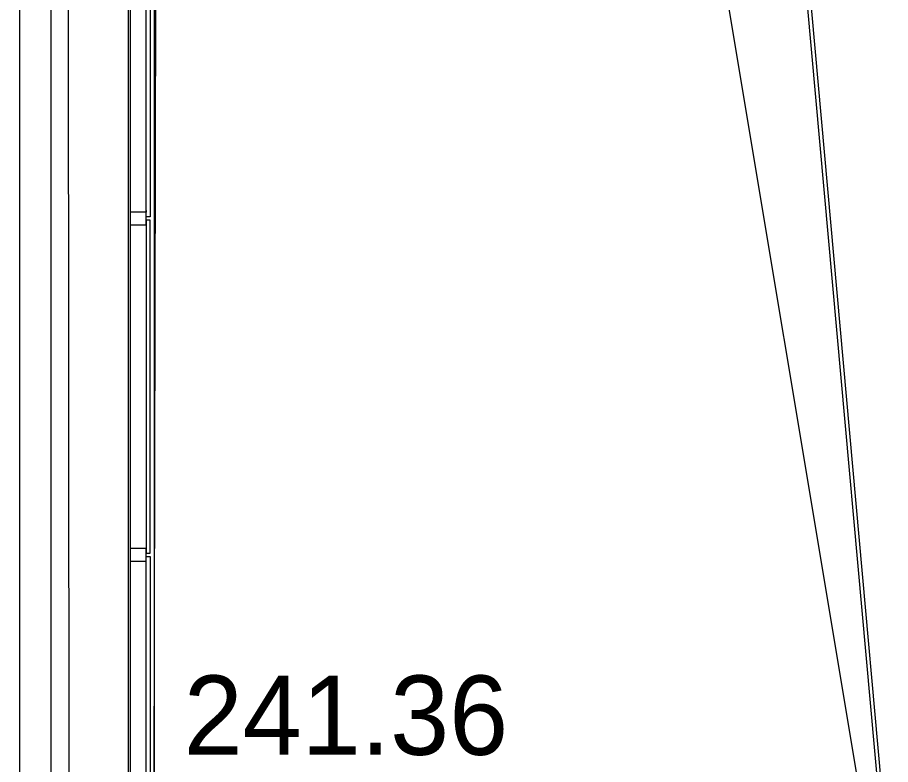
# Model space of a CAD drawing. Extents: x -264205 to -263659, y -1242401 to -1242060.
# Drawn here: x -263795.75 to -263790.25, y -1242194.76 to -1242190.06 of the extents above; entities that cross this region are included whole.
import ezdxf

# ---------------------------------------------------------------- set-up
doc = ezdxf.new("R2010")
doc.units = 0
for name, color, linetype in [('BOD_VYSKA', 7, 'Continuous'), ('KFA_SO_10-1_PLACHTY', 7, 'Continuous'), ('KFA_SO_10-1_STRECHY', 7, 'Continuous'), ('KFA_SO_10-1_TRIBUNA_C_OBVOD', 7, 'Continuous'), ('OBRUBNIKY_KOMUNIKACIE_PROJEKT', 7, 'Continuous'), ('OSI_STAVBY_KFA', 7, 'Continuous'), ('SITUACIA_DSP_2D', 7, 'Continuous')]:
    doc.layers.add(name, color=color, linetype=linetype)

msp = doc.modelspace()

# ---------------------------------------------------------------- linework, layer by layer
at = {"layer": 'KFA_SO_10-1_PLACHTY'}
msp.add_line((-263794.893, -1242195.596), (-263794.843, -1242168.189), dxfattribs=at)
for points in [[(-263795.396, -1242226.823), (-263795.427, -1242195.892), (-263795.456, -1242167.905), (-263795.427, -1242160.909), (-263795.402, -1242132.887), (-263795.428, -1242101.98)], [(-263790.3646, -1242195.4172), (-263794.826, -1242168.6678), (-263794.862, -1242168.412)]]:
    msp.add_lwpolyline(points, dxfattribs=at)
msp.add_lwpolyline([(-263792.74, -1242168.185), (-263792.715, -1242168.173), (-263790.251, -1242195.546), (-263790.271, -1242195.563)], close=True, dxfattribs=at)
at = {"layer": 'KFA_SO_10-1_STRECHY'}
msp.add_line((-263795.734, -1242227.196), (-263795.754, -1242101.588), dxfattribs=at)
at = {"layer": 'KFA_SO_10-1_TRIBUNA_C_OBVOD'}
msp.add_lwpolyline([(-263795.284, -1242101.267), (-263795.051, -1242101.819), (-263795.059, -1242226.991), (-263795.286, -1242227.548)], dxfattribs=at)
at = {"layer": 'OBRUBNIKY_KOMUNIKACIE_PROJEKT'}
msp.add_line((-263794.8928, -1242101.3822), (-263794.8928, -1242227.3822), dxfattribs=at)
at = {"layer": 'OSI_STAVBY_KFA'}
msp.add_line((-263795.5428, -1242083.2372), (-263795.5428, -1242246.7072), dxfattribs=at)
at = {"layer": 'SITUACIA_DSP_2D'}
for p, q in [((-263794.8928, -1242101.3822), (-263794.8928, -1242227.3822)), ((-263795.0428, -1242101.7691), (-263795.0428, -1242226.9954)), ((-263794.9427, -1242191.3123), (-263794.9427, -1242189.2123)), ((-263794.9177, -1242189.2123), (-263794.9177, -1242191.3123)), ((-263794.9427, -1242191.2823), (-263795.0427, -1242191.2823)), ((-263795.0427, -1242191.2823), (-263795.0427, -1242191.3623)), ((-263794.9427, -1242191.2723), (-263794.9427, -1242191.2823)), ((-263794.9427, -1242191.3623), (-263794.9427, -1242191.2723)), ((-263795.0427, -1242191.3623), (-263794.9427, -1242191.3623)), ((-263794.9177, -1242191.3123), (-263794.9427, -1242191.3123)), ((-263794.9177, -1242191.3323), (-263794.9427, -1242191.3323)), ((-263794.9427, -1242191.3323), (-263794.9427, -1242193.4323)), ((-263794.9177, -1242193.4323), (-263794.9177, -1242191.3323)), ((-263794.9427, -1242193.4023), (-263795.0427, -1242193.4023)), ((-263795.0427, -1242193.4023), (-263795.0427, -1242193.4823)), ((-263794.9427, -1242193.4423), (-263794.9427, -1242193.4023)), ((-263794.9427, -1242193.4323), (-263794.9177, -1242193.4323)), ((-263794.9427, -1242193.4823), (-263794.9427, -1242193.4423)), ((-263794.9427, -1242195.5523), (-263794.9427, -1242193.4523)), ((-263794.9427, -1242193.4523), (-263794.9177, -1242193.4523)), ((-263794.9177, -1242193.4523), (-263794.9177, -1242195.5523)), ((-263795.0427, -1242193.4823), (-263794.9427, -1242193.4823))]:
    msp.add_line(p, q, dxfattribs=at)

# ---------------------------------------------------------------- texts
at = {"layer": 'BOD_VYSKA'}
msp.add_text('241.36', height=0.5, dxfattribs=at).set_placement((-263794.706, -1242194.7029))

doc.saveas('drawing.dxf')
